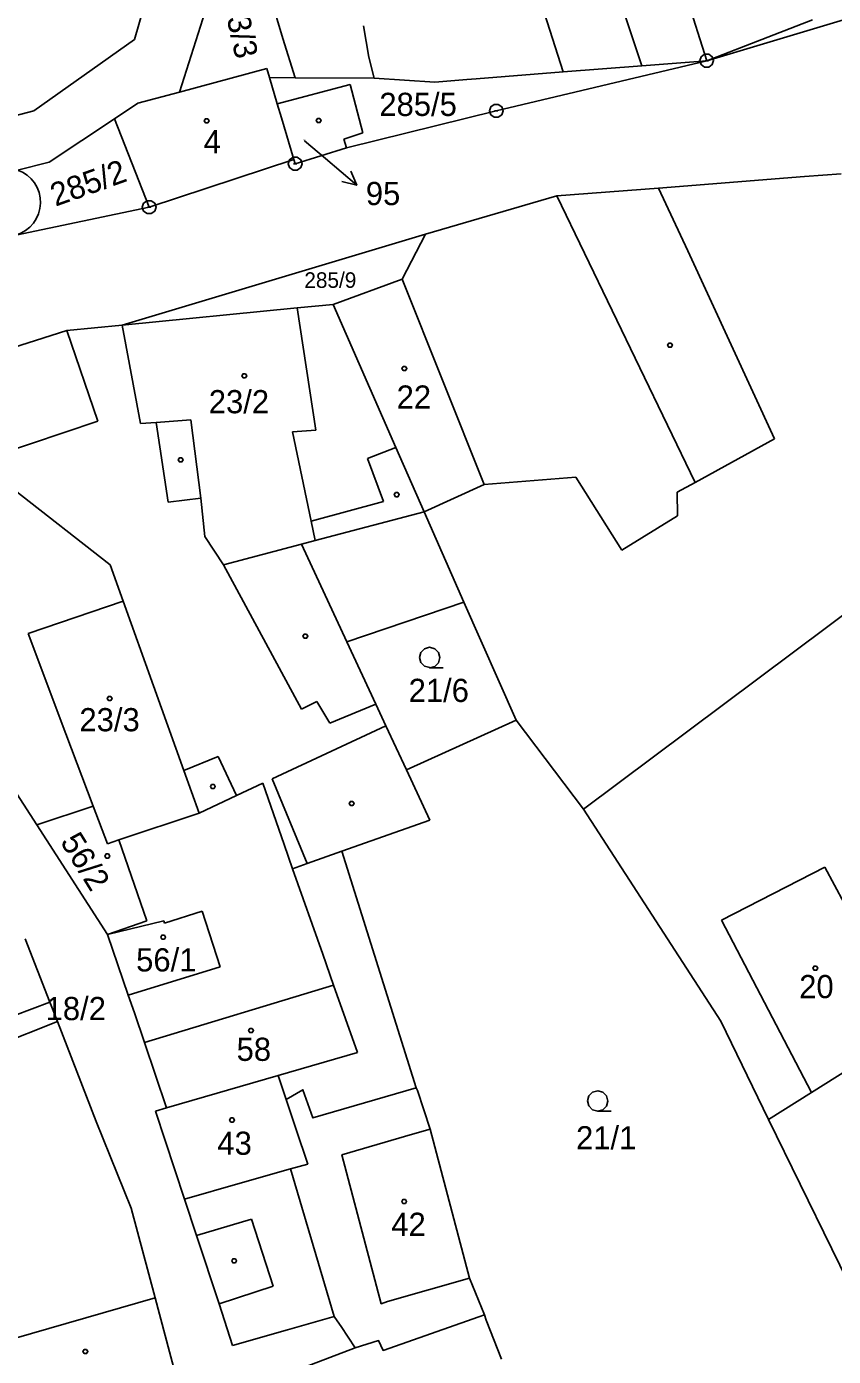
# Model space of a CAD drawing. Extents: x -779723 to -777378, y -1011169 to -1009297.
# Drawn here: x -779136.4 to -779077.2, y -1010377.2 to -1010279.6 of the extents above; entities that cross this region are included whole.
import ezdxf

# ---------------------------------------------------------------- set-up
doc = ezdxf.new("R2010")
doc.units = 0
for name, color, linetype in [('Default', 7, 'Continuous'), ('KN_HRANICE', 7, 'Continuous'), ('KN_KULTURY', 7, 'Continuous'), ('KN_PARCELY', 7, 'Continuous'), ('KN_SLUCKY', 7, 'Continuous')]:
    doc.layers.add(name, color=color, linetype=linetype)

# ---------------------------------------------------------------- blocks, each defined once
blk = doc.blocks.new('304')
at = {"layer": 'Default'}
blk.add_lwpolyline([(0, 0), (-0.38, 0.1), (-0.65, 0.37), (-0.75, 0.74), (-0.65, 1.11), (-0.38, 1.38), (-0.01, 1.48), (0.36, 1.38), (0.63, 1.11), (0.73, 0.73), (0.63, 0.35), (0.36, 0.08), (-0.02, -0.02), (0.98, -0.02)], dxfattribs=at)
blk = doc.blocks.new('NAHRADNI_SYMBOL')
at = {"layer": 'Default'}
blk.add_lwpolyline([(0.09, 0.15), (0.18, 0), (0.09, -0.15), (-0.09, -0.15), (-0.18, 0), (-0.09, 0.15), (0.09, 0.15)], dxfattribs=at)
blk = doc.blocks.new('10292')
at = {"layer": 'Default'}
blk.add_line((0, 3), (0, 0), dxfattribs=at)
blk.add_lwpolyline([(-0.5, 2), (0, 3), (0.5, 2)], dxfattribs=at)
blk = doc.blocks.new('402')
at = {"layer": 'Default'}
blk.add_lwpolyline([(0.09, 0.15), (0.18, 0), (0.09, -0.15), (-0.09, -0.15), (-0.18, 0), (-0.09, 0.15), (0.09, 0.15)], dxfattribs=at)
blk = doc.blocks.new('105')
at = {"layer": 'Default'}
blk.add_line((-0.12, 0), (0.12, 0), dxfattribs=at)
blk.add_lwpolyline([(0.15, 0.48), (0.4, 0.3), (0.5, 0.01), (0.4, -0.28), (0.15, -0.46), (-0.16, -0.46), (-0.41, -0.28), (-0.51, 0.01), (-0.41, 0.3), (-0.16, 0.48), (0.15, 0.48)], dxfattribs=at)

msp = doc.modelspace()

# ---------------------------------------------------------------- linework, layer by layer
at = {"layer": 'KN_HRANICE'}
for p, q in [((-779128.47, -1010280.58), (-779123.49, -1010263.01)), ((-779097.04, -1010282.96), (-779101.73, -1010268.16)), ((-779120.56, -1010269.87), (-779125.19, -1010284.44)), ((-779086.5, -1010282.14), (-779089.91, -1010271.43)), ((-779119.96, -1010272.44), (-779117.61, -1010280.51)), ((-779094.46, -1010272.88), (-779091.27, -1010282.5)), ((-779086.5, -1010282.14), (-779061.75, -1010274.71)), ((-779111.28, -1010281.87), (-779111.69, -1010279.58)), ((-779086.5, -1010282.14), (-779078.75, -1010279.13)), ((-779135.87, -1010285.81), (-779128.47, -1010280.58)), ((-779117.61, -1010280.51), (-779116.7, -1010283.39)), ((-779111.28, -1010281.87), (-779110.91, -1010283.41)), ((-779125.19, -1010284.44), (-779118.78, -1010282.71)), ((-779118.78, -1010282.71), (-779118.58, -1010283.38)), ((-779101.94, -1010285.82), (-779086.5, -1010282.14)), ((-779091.27, -1010282.5), (-779097.04, -1010282.96)), ((-779091.27, -1010282.5), (-779086.5, -1010282.14)), ((-779118.58, -1010283.38), (-779116.7, -1010283.39)), ((-779118.58, -1010283.38), (-779118.01, -1010285.29)), ((-779112.67, -1010283.87), (-779118.01, -1010285.29)), ((-779116.7, -1010283.39), (-779110.91, -1010283.41)), ((-779112.67, -1010283.87), (-779111.73, -1010287.42)), ((-779106.44, -1010283.7), (-779110.91, -1010283.41)), ((-779128.24, -1010285.26), (-779125.19, -1010284.44)), ((-779135.87, -1010285.81), (-779139.88, -1010286.86)), ((-779129.95, -1010286.4), (-779128.24, -1010285.26)), ((-779118.01, -1010285.29), (-779117.7, -1010286.32)), ((-779112.94, -1010288.54), (-779101.94, -1010285.82)), ((-779134.73, -1010289.57), (-779129.95, -1010286.4)), ((-779127.4, -1010292.89), (-779129.95, -1010286.4)), ((-779117.7, -1010286.32), (-779116.78, -1010289.39)), ((-779113.12, -1010287.88), (-779111.73, -1010287.42)), ((-779116.69, -1010289.7), (-779112.94, -1010288.54)), ((-779113.12, -1010287.88), (-779112.94, -1010288.54)), ((-779134.73, -1010289.57), (-779137.06, -1010290.16)), ((-779127.4, -1010292.89), (-779116.78, -1010289.39)), ((-779116.78, -1010289.39), (-779116.69, -1010289.7)), ((-779090.04, -1010291.48), (-779079.33, -1010290.64)), ((-779079.33, -1010290.64), (-779076.63, -1010290.43)), ((-779097.5, -1010292.06), (-779090.04, -1010291.48)), ((-779087.9, -1010296.09), (-779090.04, -1010291.48)), ((-779107.13, -1010294.85), (-779097.5, -1010292.06)), ((-779127.4, -1010292.89), (-779137.19, -1010294.93)), ((-779129.38, -1010301.54), (-779107.13, -1010294.85)), ((-779107.13, -1010294.85), (-779108.85, -1010298.16)), ((-779081.53, -1010309.87), (-779087.9, -1010296.09)), ((-779108.85, -1010298.16), (-779113.91, -1010300.03)), ((-779116.55, -1010300.26), (-779129.38, -1010301.54)), ((-779113.91, -1010300.03), (-779116.55, -1010300.26)), ((-779113.91, -1010300.03), (-779109.3, -1010310.52)), ((-779133.45, -1010301.92), (-779148.16, -1010306.65)), ((-779129.38, -1010301.54), (-779133.45, -1010301.92)), ((-779129.38, -1010301.54), (-779128.03, -1010308.75)), ((-779128.03, -1010308.75), (-779126.89, -1010308.67)), ((-779126.89, -1010308.67), (-779124.34, -1010308.48)), ((-779124.34, -1010308.48), (-779123.62, -1010314.23)), ((-779081.53, -1010309.87), (-779087.34, -1010313.07)), ((-779109.3, -1010310.52), (-779107.24, -1010315.22)), ((-779107.24, -1010315.22), (-779102.83, -1010313.22)), ((-779102.83, -1010313.22), (-779096.1, -1010312.69)), ((-779096.1, -1010312.69), (-779092.74, -1010318.04)), ((-779087.34, -1010313.07), (-779088.67, -1010313.8)), ((-779137.34, -1010313.6), (-779130.26, -1010319.11)), ((-779088.67, -1010313.8), (-779088.64, -1010315.52)), ((-779123.62, -1010314.23), (-779123.32, -1010317.03)), ((-779107.24, -1010315.22), (-779104.32, -1010321.87)), ((-779088.64, -1010315.52), (-779092.74, -1010318.04)), ((-779123.32, -1010317.03), (-779121.94, -1010319.13)), ((-779121.94, -1010319.13), (-779116.23, -1010317.61)), ((-779112.91, -1010324.76), (-779116.23, -1010317.61)), ((-779095.54, -1010337.04), (-779070.4, -1010318.23)), ((-779130.26, -1010319.11), (-779129.3, -1010321.78)), ((-779129.3, -1010321.78), (-779124.85, -1010334.2)), ((-779112.91, -1010324.76), (-779104.32, -1010321.87)), ((-779100.48, -1010330.51), (-779104.32, -1010321.87)), ((-779110.78, -1010329.34), (-779112.91, -1010324.76)), ((-779135.65, -1010338.2), (-779142.22, -1010328.02)), ((-779110.04, -1010330.92), (-779110.78, -1010329.34)), ((-779108.53, -1010334.17), (-779100.48, -1010330.51)), ((-779100.48, -1010330.51), (-779095.54, -1010337.04)), ((-779108.53, -1010334.17), (-779110.04, -1010330.92)), ((-779124.85, -1010334.2), (-779123.73, -1010337.33)), ((-779106.82, -1010337.84), (-779108.53, -1010334.17)), ((-779120.99, -1010336.04), (-779119.07, -1010335.14)), ((-779117.5, -1010339.64), (-779119.07, -1010335.14)), ((-779123.73, -1010337.33), (-779120.99, -1010336.04)), ((-779135.65, -1010338.2), (-779131.51, -1010336.82)), ((-779131.51, -1010336.82), (-779130.47, -1010339.58)), ((-779129.62, -1010339.3), (-779123.73, -1010337.33)), ((-779085.48, -1010352.6), (-779095.54, -1010337.04)), ((-779130.45, -1010346.25), (-779135.65, -1010338.2)), ((-779113.27, -1010340.13), (-779106.82, -1010337.84)), ((-779130.47, -1010339.58), (-779129.62, -1010339.3)), ((-779129.62, -1010339.3), (-779127.57, -1010345.23)), ((-779116.88, -1010341.42), (-779117.5, -1010339.64)), ((-779115.81, -1010341.04), (-779113.27, -1010340.13)), ((-779113.27, -1010340.13), (-779107.81, -1010357.49)), ((-779116.88, -1010341.42), (-779115.81, -1010341.04)), ((-779116.88, -1010341.42), (-779114.67, -1010347.67)), ((-779085.43, -1010345.18), (-779077.83, -1010341.29)), ((-779077.83, -1010341.29), (-779074.32, -1010347.9)), ((-779130.45, -1010346.25), (-779127.57, -1010345.23)), ((-779085.43, -1010345.18), (-779078.82, -1010357.83)), ((-779130.45, -1010346.25), (-779128.94, -1010350.68)), ((-779136.5, -1010346.55), (-779134.69, -1010351.21)), ((-779114.67, -1010347.67), (-779113.87, -1010349.95)), ((-779127.75, -1010354.15), (-779113.87, -1010349.95)), ((-779134.69, -1010351.21), (-779134.14, -1010352.63)), ((-779128.94, -1010350.68), (-779128.49, -1010351.99)), ((-779127.75, -1010354.15), (-779128.49, -1010351.99)), ((-779149.85, -1010358.82), (-779134.14, -1010352.63)), ((-779134.14, -1010352.63), (-779131.3, -1010359.95)), ((-779081.96, -1010359.81), (-779085.48, -1010352.6)), ((-779071.49, -1010353.21), (-779078.82, -1010357.83)), ((-779126.12, -1010358.95), (-779127.75, -1010354.15)), ((-779126.12, -1010358.95), (-779117.94, -1010356.58)), ((-779117.94, -1010356.58), (-779117.35, -1010358.34)), ((-779107.81, -1010357.49), (-779107.71, -1010357.68)), ((-779106.8, -1010360.53), (-779107.71, -1010357.68)), ((-779078.82, -1010357.83), (-779081.96, -1010359.81)), ((-779126.93, -1010359.19), (-779126.12, -1010358.95)), ((-779117.35, -1010358.34), (-779116.64, -1010360.46)), ((-779131.3, -1010359.95), (-779128.72, -1010366.32)), ((-779124.81, -1010365.65), (-779126.93, -1010359.19)), ((-779071.95, -1010380.31), (-779081.96, -1010359.81)), ((-779116.64, -1010360.46), (-779115.76, -1010363.08)), ((-779106.8, -1010360.53), (-779103.91, -1010371.45)), ((-779117.03, -1010363.44), (-779115.76, -1010363.08)), ((-779117.03, -1010363.44), (-779113.83, -1010374.27)), ((-779123.93, -1010368.31), (-779124.81, -1010365.65)), ((-779128.72, -1010366.32), (-779126.96, -1010372.9)), ((-779122.28, -1010373.34), (-779123.93, -1010368.31)), ((-779102.81, -1010374.14), (-779103.91, -1010371.45)), ((-779138.68, -1010376.27), (-779126.96, -1010372.9)), ((-779126.96, -1010372.9), (-779125.49, -1010378.42)), ((-779121.28, -1010376.38), (-779122.28, -1010373.34)), ((-779117.26, -1010375.24), (-779113.83, -1010374.27)), ((-779102.69, -1010374.53), (-779102.81, -1010374.14)), ((-779101.55, -1010377.4), (-779102.69, -1010374.53)), ((-779121.28, -1010376.38), (-779117.26, -1010375.24)), ((-779116, -1010377.97), (-779112.28, -1010376.55))]:
    msp.add_line(p, q, dxfattribs=at)
for points in [[(-779097.04, -1010282.96), (-779103.42, -1010283.46), (-779104.11, -1010283.52), (-779106.44, -1010283.7)], [(-779107.81, -1010357.49), (-779115.4, -1010359.69), (-779116.13, -1010357.63), (-779117.35, -1010358.34)], [(-779113.83, -1010374.27), (-779113.61, -1010374.59), (-779113.33, -1010375), (-779112.28, -1010376.55)], [(-779112.28, -1010376.55), (-779110.58, -1010376.03), (-779110.25, -1010376.75), (-779103.23, -1010374.29), (-779102.81, -1010374.14)]]:
    msp.add_lwpolyline(points, dxfattribs=at)
msp.add_arc((-779137.87, -1010292.52), 2.5, 285.7463, 71.13143, dxfattribs=at)
at = {"layer": 'KN_PARCELY'}
msp.add_line((-779116, -1010288.01), (-779114.46, -1010289.32), dxfattribs=at)
at = {"layer": 'KN_SLUCKY'}
for p, q in [((-779097.5, -1010292.06), (-779087.34, -1010313.07)), ((-779108.85, -1010298.16), (-779102.83, -1010313.22)), ((-779116.55, -1010300.26), (-779115.17, -1010309.24)), ((-779133.45, -1010301.92), (-779131.16, -1010308.58)), ((-779140.22, -1010311.61), (-779131.16, -1010308.58)), ((-779126.89, -1010308.67), (-779126, -1010314.52)), ((-779115.17, -1010309.24), (-779116.88, -1010309.36)), ((-779116.88, -1010309.36), (-779115.53, -1010315.91)), ((-779111.38, -1010311.33), (-779109.3, -1010310.52)), ((-779110.21, -1010314.47), (-779111.38, -1010311.33)), ((-779126, -1010314.52), (-779123.62, -1010314.23)), ((-779115.53, -1010315.91), (-779110.21, -1010314.47)), ((-779115.53, -1010315.91), (-779115.23, -1010317.34)), ((-779115.23, -1010317.34), (-779107.24, -1010315.22)), ((-779116.23, -1010317.61), (-779115.23, -1010317.34)), ((-779121.94, -1010319.13), (-779116.22, -1010329.71)), ((-779136.29, -1010324.15), (-779129.3, -1010321.78)), ((-779136.29, -1010324.15), (-779133.52, -1010331.51)), ((-779116.22, -1010329.71), (-779115.11, -1010329.15)), ((-779115.11, -1010329.15), (-779114.16, -1010330.74)), ((-779114.16, -1010330.74), (-779110.78, -1010329.34)), ((-779133.52, -1010331.51), (-779131.51, -1010336.82)), ((-779118.38, -1010334.82), (-779110.04, -1010330.92)), ((-779124.85, -1010334.2), (-779122.33, -1010333.18)), ((-779122.33, -1010333.18), (-779120.99, -1010336.04)), ((-779118.38, -1010334.82), (-779115.81, -1010341.04)), ((-779130.45, -1010346.25), (-779126.34, -1010345.23)), ((-779126.34, -1010345.23), (-779126.27, -1010345.4)), ((-779126.27, -1010345.4), (-779123.51, -1010344.52)), ((-779123.51, -1010344.52), (-779122.2, -1010348.62)), ((-779122.2, -1010348.62), (-779128.94, -1010350.68)), ((-779113.87, -1010349.95), (-779112.12, -1010354.89)), ((-779148.04, -1010356.21), (-779134.69, -1010351.21)), ((-779117.94, -1010356.58), (-779112.12, -1010354.89)), ((-779120.72, -1010364.49), (-779117.03, -1010363.44)), ((-779124.81, -1010365.65), (-779120.72, -1010364.49)), ((-779123.93, -1010368.31), (-779119.9, -1010367.12)), ((-779119.9, -1010367.12), (-779118.3, -1010372.03)), ((-779118.3, -1010372.03), (-779122.28, -1010373.34))]:
    msp.add_line(p, q, dxfattribs=at)
msp.add_lwpolyline([(-779106.8, -1010360.53), (-779108.08, -1010360.89), (-779113.27, -1010362.41), (-779110.38, -1010373.33), (-779109.92, -1010373.16), (-779103.91, -1010371.45)], dxfattribs=at)

# ---------------------------------------------------------------- block references
at = {"layer": 'KN_KULTURY'}
for name, p in [('402', (-779123.19, -1010286.54)), ('NAHRADNI_SYMBOL', (-779114.97, -1010286.53)), ('402', (-779089.2, -1010303.01)), ('402', (-779120.43, -1010305.25)), ('402', (-779108.68, -1010304.72)), ('402', (-779125.09, -1010311.42)), ('402', (-779109.24, -1010313.97)), ('402', (-779115.94, -1010324.35)), ('304', (-779106.82, -1010326.65)), ('402', (-779130.3, -1010328.92)), ('402', (-779122.73, -1010335.39)), ('402', (-779112.55, -1010336.62)), ('402', (-779130.47, -1010340.48)), ('402', (-779126.38, -1010346.43)), ('402', (-779078.54, -1010348.71)), ('402', (-779119.93, -1010353.29)), ('304', (-779094.49, -1010359.19)), ('402', (-779121.32, -1010359.85)), ('402', (-779108.7, -1010365.82)), ('402', (-779121.17, -1010370.18)), ('NAHRADNI_SYMBOL', (-779132.08, -1010376.83))]:
    msp.add_blockref(name, p, dxfattribs=at)
at = {"layer": 'KN_PARCELY'}
for p in [(-779086.5, -1010282.14), (-779101.94, -1010285.82), (-779116.69, -1010289.7), (-779127.4, -1010292.89)]:
    msp.add_blockref('105', p, dxfattribs=at)
at = {"layer": 'KN_PARCELY', "rotation": -130.41581100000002}
msp.add_blockref('10292', (-779114.46, -1010289.32), dxfattribs=at)

# ---------------------------------------------------------------- texts
at = {"layer": 'KN_PARCELY'}
for s, rotation, p in [('303/3', 282.296, (-779122.26, -1010276.53)), ('285/2', 19.595, (-779134.28, -1010292.85)), ('56/2', 301.662, (-779133.97, -1010339.43))]:
    msp.add_text(s, height=1.7, rotation=rotation, dxfattribs=at).set_placement(p)
for s, height, p in [('285/5', 1.7, (-779110.52, -1010286.19)), ('4', 1.7, (-779123.41, -1010288.93)), ('95', 0.1, (-779116.095, -1010288.01)), ('95', 1.7, (-779111.51, -1010292.73)), ('285/9', 1.14, (-779116.021, -1010298.8)), ('23/2', 1.7, (-779123.03, -1010308)), ('22', 1.7, (-779109.25, -1010307.66)), ('21/6', 1.7, (-779108.37, -1010329.18)), ('23/3', 1.7, (-779132.52, -1010331.33)), ('56/1', 1.7, (-779128.36, -1010348.95)), ('20', 1.7, (-779079.72, -1010350.91)), ('18/2', 1.7, (-779135, -1010352.52)), ('58', 1.7, (-779120.99, -1010355.51)), ('43', 1.7, (-779122.4, -1010362.4)), ('21/1', 1.7, (-779096.09, -1010362)), ('42', 1.7, (-779109.64, -1010368.35))]:
    msp.add_text(s, height=height, dxfattribs=at).set_placement(p)

doc.saveas('drawing.dxf')
